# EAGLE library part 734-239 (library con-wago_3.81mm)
Serie 734, Stiftleiste (für Leiterplatten) Einlötstift gerade 1 x 1 mm / Series 734, Male header (for PCBs) Straight solder pin 1 x 1 mm Polzahl / Pole No.: 7 Rastermaß / Pitch: 3.81 mm Bemessungsspannung / Rated Voltage: 160 V Nennstrom / Nominal Current: 10 A Lötstiftlänge: / Solder Pin Length: 4.5 mm Farbe / Color: orange / orange Stand: 01.01.2012. Die jeweils aktuellen Daten zu diesem Artikel finden Sie in unserem Produktkatalog, den Sie unter www.wago.com einsehen können. As of: 01/01/2012. Please find the newest data for this article in our product catalogue, which can be viewed under www.wago.com.
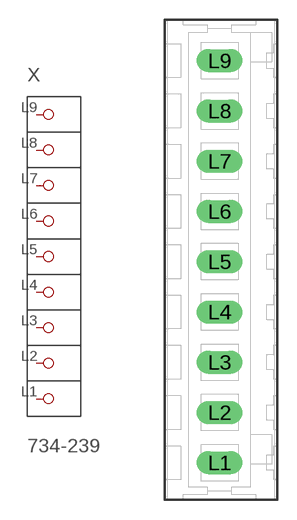
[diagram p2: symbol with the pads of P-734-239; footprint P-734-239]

Designator prefix X

## 734-239  [P-734-239]
L1  P1
L2  P2
L3  P3
L4  P4
L5  P5
L6  P6
L7  P7
L8  P8
L9  P9

## Footprint P-734-239 (pad centres in mm)
drill 1.15 long: L1 -0.1,-15.39; L2 -0.1,-11.58; L3 -0.1,-7.77; L4 -0.1,-3.96; L5 -0.1,-0.15; L6 -0.1,3.66; L7 -0.1,7.47; L8 -0.1,11.28; L9 -0.1,15.09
